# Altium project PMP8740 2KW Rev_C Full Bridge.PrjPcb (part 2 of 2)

## Sheet PMP8740 2KW Rev_C Full Bridge Control Section-A Schematic.SchDoc: Control
size 431 x 279 mm; Date: Not shown in title block; ApprovedBy: Not shown in title block; CheckedBy: Not shown in title block; Author: Not shown in title block; CompanyName: Not shown in title block; DrawnBy: R. Scibilia; Engineer: Not shown in title block; Organization: Not shown in title block; Address1: Not shown in title block; Address2: Not shown in title block; Address3: Not shown in title block; Address4: Not shown in title block; DocumentNumber: 1; Revision: Use project parameter SCH_Rev; SheetNumber: 1; SheetTotal: 1; PageSetup: Record=PageOptions|CenterHorizontal=True|CenterVertical=True|PrintScale=1.00|XCorrection=1.00|YCorrection=1.00|PrintKind=0|BorderSize=5000000|LeftOffset=0|BottomOffset=0|Orientation=2|PaperLength=1000|PaperWidth=1000|Scale=100|PaperSource=15|PrintQuality=600|MediaType=1|DitherType=10|PaperKind=Letter|PrintScaleMode=1
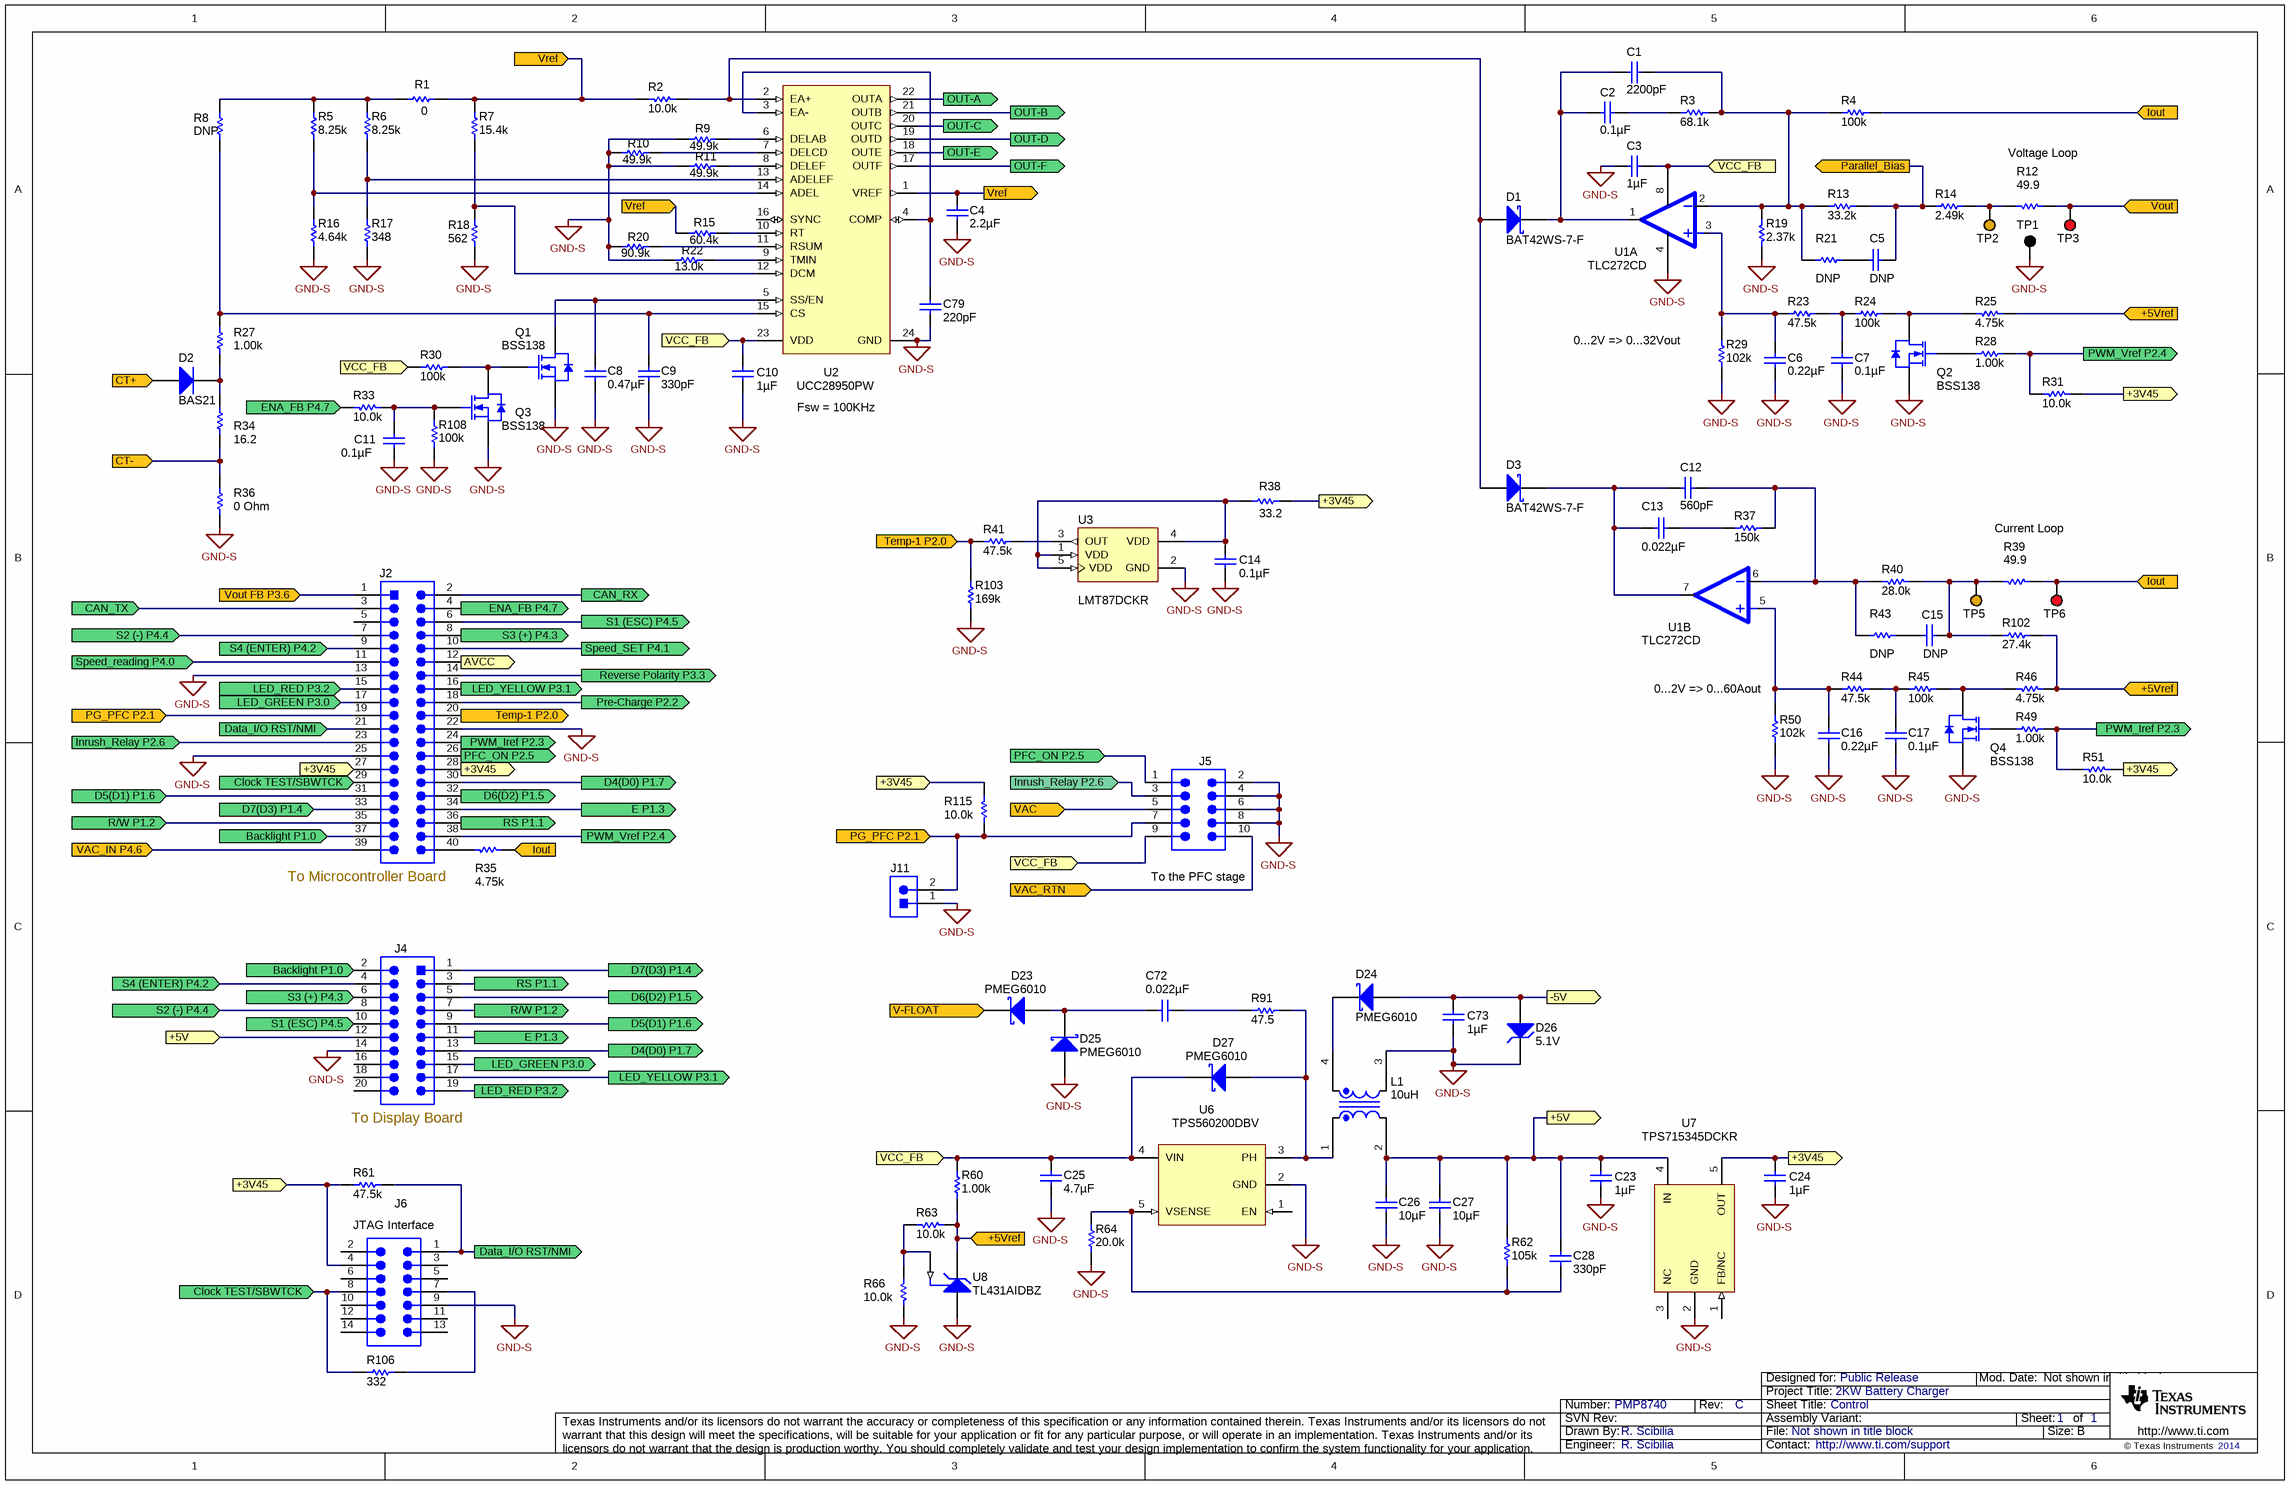
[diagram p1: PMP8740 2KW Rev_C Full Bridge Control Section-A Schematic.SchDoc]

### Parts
C1  ValueDisplayed: 2200pF  [0603]  (hidden comment: C1608C0G1H222J)
C2  ValueDisplayed: 0.1µF  [0603]  (hidden comment: C1608X7R1H104K)
C3  ValueDisplayed: 1µF  [0603]  (hidden comment: C1608X7R1E105K080AB)
C4  ValueDisplayed: 2.2µF  [0805_HV]  (hidden comment: C2012X7R1C225K)
C5  DNP  [0603]
C6  ValueDisplayed: 0.22µF  [0603]  (hidden comment: C1608X7R1C224K)
C7  ValueDisplayed: 0.1µF  [0603]  (hidden comment: C1608X7R1H104K)
C8  ValueDisplayed: 0.47µF  [0805_HV]  (hidden comment: C2012X7R1C474K)
C9  ValueDisplayed: 330pF  [0603]  (hidden comment: C1608C0G1H331J)
C10  ValueDisplayed: 1µF  [0603]  (hidden comment: C1608X7R1E105K080AB)
C11  ValueDisplayed: 0.1µF  [0603]  (hidden comment: C1608X7R1H104K)
C12  ValueDisplayed: 560pF  [0603]  (hidden comment: C1608C0G1H561J)
C13  ValueDisplayed: 0.022µF  [0603]  (hidden comment: C1608X7R2A223K)
C14  ValueDisplayed: 0.1µF  [0603]  (hidden comment: C1608X7R1H104K)
C15  DNP  [0603]
C16  ValueDisplayed: 0.22µF  [0603]  (hidden comment: C1608X7R1C224K)
C17  ValueDisplayed: 0.1µF  [0603]  (hidden comment: C1608X7R1H104K)
C23  ValueDisplayed: 1µF  [0603]  (hidden comment: C1608X7R1E105K080AB)
C24  ValueDisplayed: 1µF  [0603]  (hidden comment: C1608X7R1E105K080AB)
C25  ValueDisplayed: 4.7µF  [1206]  (hidden comment: C3216X7R1E475K)
C26  ValueDisplayed: 10µF  [1206]  (hidden comment: C3216X7R1A106M)
C27  ValueDisplayed: 10µF  [1206]  (hidden comment: C3216X7R1A106M)
C28  ValueDisplayed: 330pF  [0603]  (hidden comment: C1608C0G1H331J)
C72  ValueDisplayed: 0.022µF  [0603]  (hidden comment: C1608X7R2A223K)
C73  ValueDisplayed: 1µF  [0603]  (hidden comment: C1608X7R1E105K080AB)
C79  ValueDisplayed: 220pF  [0603]  (hidden comment: C0603C221J5GACTU)
D1  BAT42WS-7-F  [sod-323]
D2  value BAS21  [SOT-23]  (hidden comment: BAS21-7-F)
D3  BAT42WS-7-F  [sod-323]
D23  value PMEG6010  [SOD-123F]  (hidden comment: PMEG6010CEH,115)
D24  value PMEG6010  [SOD-123F]  (hidden comment: PMEG6010CEH,115)
D25  value PMEG6010  [SOD-123F]  (hidden comment: PMEG6010CEH,115)
D26  value 5.1V  [SOD-123]  (hidden comment: MMSZ4689T1G)
D27  value PMEG6010  [SOD-123F]  (hidden comment: PMEG6010CEH,115)
J2  87758-4016  [MOLEX_87758-4016]  (value not drawn)
J4  66506-072LF  [CONN_66506-072LF]  (value not drawn)
J5  5103308-1  [CONN_5103308-1]  (value not drawn)
J6  SBH11-PBPC-D07-ST-BK  [CONN_SBH11-PBPC-D07-ST-BK]  (value not drawn)
J11  5-146261-1  [CONN_5-146261-1]  (value not drawn)
L1  value 10uH  [WE-DD_7332]  (hidden comment: 744878100)
Q1  BSS138  [SOT-23]
Q2  BSS138  [SOT-23]
Q3  BSS138  [SOT-23]
Q4  BSS138  [SOT-23]
R1  value 0  [0603]  (hidden comment: CRCW06031R00FKEA)
R2  value 10.0k  [0603]  (hidden comment: CRCW060310K0FKEA)
R3  ValueDisplayed: 68.1k  [0603]  (hidden comment: CRCW060368K1FKEA)
R4  value 100k  [0603]  (hidden comment: CRCW0603100KFKEA)
R5  value 8.25k  [0603]  (hidden comment: CRCW06038K25FKEA)
R6  value 8.25k  [0603]  (hidden comment: CRCW06038K25FKEA)
R7  value 15.4k  [0603]  (hidden comment: CRCW060315K4FKEA)
R8  value DNP  [0603]  (hidden comment: Do Not Populate)
R9  value 49.9k  [0603]  (hidden comment: CRCW060349K9FKEA)
R10  value 49.9k  [0603]  (hidden comment: CRCW060349K9FKEA)
R11  value 49.9k  [0603]  (hidden comment: CRCW060349K9FKEA)
R12  value 49.9  [0603]  (hidden comment: CRCW060349R9FKEA)
R13  ValueDisplayed: 33.2k  [1206]  (hidden comment: CRCW120633K2FKEA)
R14  value 2.49k  [0603]  (hidden comment: CRCW06032K49FKEA)
R15  value 60.4k  [0603]  (hidden comment: CRCW060360K4FKEA)
R16  value 4.64k  [0603]  (hidden comment: CRCW06034K64FKEA)
R17  value 348  [0603]  (hidden comment: CRCW0603348RFKEA)
R18  ValueDisplayed: 562  [0603]  (hidden comment: CRCW0603562RFKEA)
R19  value 2.37k  [0603]  (hidden comment: CRCW06032K37FKEA)
R20  value 90.9k  [0603]  (hidden comment: CRCW060390K9FKEA)
R21  DNP  [0603]
R22  value 13.0k  [0603]  (hidden comment: CRCW060313K0FKEA)
R23  ValueDisplayed: 47.5k  [0603]  (hidden comment: CRCW060347K5FKEA)
R24  value 100k  [0603]  (hidden comment: CRCW0603100KFKEA)
R25  value 4.75k  [0603]  (hidden comment: CRCW06034K75FKEA)
R27  value 1.00k  [0603]  (hidden comment: CRCW06031K00FKEA)
R28  value 1.00k  [0603]  (hidden comment: CRCW06031K00FKEA)
R29  ValueDisplayed: 102k  [0603]  (hidden comment: CRCW0603102KFKEA)
R30  value 100k  [0603]  (hidden comment: CRCW0603100KFKEA)
R31  value 10.0k  [0603]  (hidden comment: CRCW060310K0FKEA)
R33  value 10.0k  [0603]  (hidden comment: CRCW060310K0FKEA)
R34  ValueDisplayed: 16.2  [2512]  (hidden comment: CRCW251216R2FKEG)
R35  value 4.75k  [0603]  (hidden comment: CRCW06034K75FKEA)
R36  0 Ohm  [1206]
R37  ValueDisplayed: 150k  [0603]  (hidden comment: CRCW0603150KFKEA)
R38  value 33.2  [0603]  (hidden comment: CRCW060333R2FKEA)
R39  value 49.9  [0603]  (hidden comment: CRCW060349R9FKEA)
R40  value 28.0k  [0603]  (hidden comment: CRCW060328K0FKEA)
R41  ValueDisplayed: 47.5k  [0603]  (hidden comment: CRCW060347K5FKEA)
R43  DNP  [0603]
R44  ValueDisplayed: 47.5k  [0603]  (hidden comment: CRCW060347K5FKEA)
R45  value 100k  [0603]  (hidden comment: CRCW0603100KFKEA)
R46  value 4.75k  [0603]  (hidden comment: CRCW06034K75FKEA)
R49  value 1.00k  [0603]  (hidden comment: CRCW06031K00FKEA)
R50  ValueDisplayed: 102k  [0603]  (hidden comment: CRCW0603102KFKEA)
R51  value 10.0k  [0603]  (hidden comment: CRCW060310K0FKEA)
R60  value 1.00k  [0603]  (hidden comment: CRCW06031K00FKEA)
R61  ValueDisplayed: 47.5k  [0603]  (hidden comment: CRCW060347K5FKEA)
R62  value 105k  [0603]  (hidden comment: CRCW0603105KFKEA)
R63  value 10.0k  [0603]  (hidden comment: CRCW060310K0FKEA)
R64  value 20.0k  [0603]  (hidden comment: CRCW060320K0FKEA)
R66  value 10.0k  [0603]  (hidden comment: CRCW060310K0FKEA)
R91  value 47.5  [0805_HV]  (hidden comment: CRCW080547R5FKEA)
R102  ValueDisplayed: 27.4k  [0603]  (hidden comment: CRCW060327K4FKEA)
R103  ValueDisplayed: 169k  [0603]  (hidden comment: CRCW0603169KFKEA)
R106  value 332  [0603]  (hidden comment: RC0603FR-07332RL)
R108  value 100k  [0603]  (hidden comment: CRCW0603100KFKEA)
R115  value 10.0k  [0603]  (hidden comment: CRCW060310K0FKEA)
TP1  5006  [Keystone5006]  (value not drawn)
TP2  5008  [Keystone5008]  (value not drawn)
TP3  5005  [Keystone5005]  (value not drawn)
TP5  5008  [Keystone5008]  (value not drawn)
TP6  5005  [Keystone5005]  (value not drawn)
U1  TLC272CD  [SO8]  (parts A,B of 2)
U2  UCC28950PW  [PW0024A_N]
U3  value LMT87DCKR  [MAA05A_N]  (hidden comment: LM94022QBIMG)
U6  TPS560200DBV  [DBV0005A_N]
U7  TPS715345DCKR  [DCK0005A_N]
U8  TL431AIDBZ  [DBZ0003A_N]

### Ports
+3V45, +5V, +5Vref, -5V, AVCC, Backlight P1.0, CAN_RX, CAN_TX, Clock TEST/SBWTCK, CT+, CT-, D4(D0) P1.7, D5(D1) P1.6, D6(D2) P1.5, D7(D3) P1.4, Data_I/O RST/NMI, E P1.3, ENA_FB P4.7, Inrush_Relay P2.6, Iout, LED_GREEN P3.0, LED_RED P3.2, LED_YELLOW P3.1, OUT-A, OUT-B, OUT-C, OUT-D, OUT-E, OUT-F, Parallel_Bias, PFC_ON P2.5, PG_PFC P2.1, Pre-Charge P2.2, PWM_Iref P2.3, PWM_Vref P2.4, R/W P1.2, Reverse Polarity P3.3, RS P1.1, S1 (ESC) P4.5, S2 (-) P4.4, S3 (+) P4.3, S4 (ENTER) P4.2, Speed_reading P4.0, Speed_SET P4.1, Temp-1 P2.0, V-FLOAT, VAC, VAC_IN P4.6, VAC_RTN, VCC_FB, Vout, Vout FB P3.6, Vref

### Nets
GND-S: C3.1 C4.2 C6.2 C7.2 C8.2 C9.2 C10.2 C11.2 C14.2 C16.2 C17.2 C23.2 C24.2 C25.2 C26.2 C27.2 C73.2 C79.2 D25.2(A) D26.1(K) J2.13 J2.22 J2.25 J4.14 J5.2 J5.4 J5.6 J5.8 J6.9 J11.1 L1.3 Q1.2(S) Q2.2(S) Q3.2(S) Q4.2(S) R9.1 R10.1 R11.1 R16.1 R17.1 R18.1 R19.1 R20.1 R22.1 R29.1 R36.2 R50.1 R64.1 R66.1 R103.1 R108.1 TP1.1 U1.4(GND) U2.24(GND) U3.2(GND) U6.2(GND) U7.2(GND) U8.3(ANODE)
+3V45: C24.1 J2.27 J2.28 J6.4 R31.2 R38.2 R51.2 R61.1 R115.2 U7.5(OUT) ; port +3V45
+5V: C23.1 C26.1 C27.1 C28.1 J4.12 L1.2 R62.2 U7.4(IN) ; port +5V
+5Vref: R25.1 R46.1 R60.1 R63.2 R102.2 U8.1(CATHODE) ; port +5Vref
-5V: C73.1 D24.2(A) D26.2(A) ; port -5V
AVCC: J2.12 ; port AVCC
Backlight P1.0: J2.37 J4.2 ; port Backlight P1.0
CAN_RX: J2.2 ; port CAN_RX
CAN_TX: J2.3 ; port CAN_TX
Clock TEST/SBWTCK: J2.29 J6.8 R106.1 ; port Clock TEST/SBWTCK
CT+: D2.1(A) ; port CT+
CT-: R34.1 R36.1 ; port CT-
D4(D0) P1.7: J2.30 J4.13 ; port D4(D0) P1.7
D5(D1) P1.6: J2.31 J4.9 ; port D5(D1) P1.6
D6(D2) P1.5: J2.32 J4.5 ; port D6(D2) P1.5
D7(D3) P1.4: J2.33 J4.1 ; port D7(D3) P1.4
Data_I/O RST/NMI: J2.21 J6.1 R61.2 ; port Data_I/O RST/NMI
E P1.3: J2.34 J4.11 ; port E P1.3
ENA_FB P4.7: J2.4 R33.2 ; port ENA_FB P4.7
Inrush_Relay P2.6: J2.23 J5.3 ; port Inrush_Relay P2.6
Iout: R4.1 R35.2 R39.1 TP6.1 ; port Iout
LED_GREEN P3.0: J2.17 J4.15 ; port LED_GREEN P3.0
LED_RED P3.2: J2.15 J4.19 ; port LED_RED P3.2
LED_YELLOW P3.1: J2.16 J4.17 ; port LED_YELLOW P3.1
OUT-A: U2.22(OUTA) ; port OUT-A
OUT-B: U2.21(OUTB) ; port OUT-B
OUT-C: U2.20(OUTC) ; port OUT-C
OUT-D: U2.19(OUTD) ; port OUT-D
OUT-E: U2.18(OUTE) ; port OUT-E
OUT-F: U2.17(OUTF) ; port OUT-F
Parallel_Bias: C5.1 R13.2 R14.2 ; port Parallel_Bias
PFC_ON P2.5: J2.26 J5.1 ; port PFC_ON P2.5
PG_PFC P2.1: J2.19 J5.7 J11.2 R115.1 ; port PG_PFC P2.1
Pre-Charge P2.2: J2.18 ; port Pre-Charge P2.2
PWM_Iref P2.3: J2.24 R49.1 R51.1 ; port PWM_Iref P2.3
PWM_Vref P2.4: J2.38 R28.1 R31.1 ; port PWM_Vref P2.4
R/W P1.2: J2.35 J4.7 ; port R/W P1.2
Reverse Polarity P3.3: J2.14 ; port Reverse Polarity P3.3
RS P1.1: J2.36 J4.3 ; port RS P1.1
S1 (ESC) P4.5: J2.6 J4.10 ; port S1 (ESC) P4.5
S2 (-) P4.4: J2.7 J4.8 ; port S2 (-) P4.4
S3 (+) P4.3: J2.8 J4.6 ; port S3 (+) P4.3
S4 (ENTER) P4.2: J2.9 J4.4 ; port S4 (ENTER) P4.2
Speed_reading P4.0: J2.11 ; port Speed_reading P4.0
Speed_SET P4.1: J2.10 ; port Speed_SET P4.1
Temp-1 P2.0: J2.20 R41.2 R103.2 ; port Temp-1 P2.0
V-FLOAT: D23.1(K) ; port V-FLOAT
VAC: J5.5 ; port VAC
VAC_IN P4.6: J2.39 ; port VAC_IN P4.6
VAC_RTN: J5.10 ; port VAC_RTN
VCC_FB: C3.2 C10.1 C25.1 D27.1(K) J5.9 R30.1 R60.2 U1.8(VCC) U2.23(VDD) U6.4(VIN) ; port VCC_FB
Vout: R12.1 TP3.1 ; port Vout
Vout FB P3.6: J2.1 ; port Vout FB P3.6
Vref: C4.1 R1.2 R2.2 R7.2 R15.2 U2.1(VREF) ; port Vref
NetC1_1: C1.1 C2.1 D1.1(K) U1.1(OUT1)
NetC1_2: C1.2 R3.1 R4.2 R13.1 R19.2 R21.1 U1.2(IN-)
NetC2_2: C2.2 R3.2
NetC5_2: C5.2 R21.2
NetC6_1: C6.1 R23.1 R29.2 U1.3(IN+)
NetC7_1: C7.1 R23.2 R24.1
NetC8_1: C8.1 Q1.3(D) U2.5(SS/EN)
NetC9_1: C9.1 R8.1 R27.1 U2.15(CS)
NetC11_1: C11.1 Q3.1(G) R33.1 R108.2
NetC12_1: C12.1 C13.1 D3.1(K) U1.7(OUT)
NetC12_2: C12.2 R37.1 R40.2 R43.1 U1.6(IN-)
NetC13_2: C13.2 R37.2
NetC14_1: C14.1 R38.1 U3.1(VDD) U3.4(VDD) U3.5(VDD)
NetC15_1: C15.1 R39.2 R40.1 R102.1 TP5.1
NetC15_2: C15.2 R43.2
NetC16_1: C16.1 R44.1 R50.2 U1.5(IN+)
NetC17_1: C17.1 R44.2 R45.1
NetC28_2: C28.2 R62.1 R64.2 U6.5(VSENSE)
NetC72_1: C72.1 D23.2(A) D25.1(K)
NetC72_2: C72.2 R91.1
NetC79_1: C79.1 U2.3(EA-) U2.4(COMP)
NetD1_2: D1.2(A) D3.2(A) R2.1 U2.2(EA+)
NetD2_3: D2.3(K) R27.2 R34.2
NetD24_1: D24.1(K) L1.4
NetD27_2: D27.2(A) L1.1 R91.2 U6.3(PH)
NetJ2_40: J2.40 R35.1
NetJ6_7: J6.7 R106.2
NetQ1_1: Q1.1(G) Q3.3(D) R30.2
NetQ2_1: Q2.1(G) R28.2
NetQ2_3: Q2.3(D) R24.2 R25.2
NetQ4_1: Q4.1(G) R49.2
NetQ4_3: Q4.3(D) R45.2 R46.2
NetR1_1: R1.1 R5.2 R6.2 R8.2
NetR5_1: R5.1 R16.2 U2.14(ADEL)
NetR6_1: R6.1 R17.2 U2.13(ADELEF)
NetR7_1: R7.1 R18.2 U2.12(DCM)
NetR9_2: R9.2 U2.6(DELAB)
NetR10_2: R10.2 U2.7(DELCD)
NetR11_2: R11.2 U2.8(DELEF)
NetR12_2: R12.2 R14.1 TP2.1
NetR15_1: R15.1 U2.10(RT)
NetR20_2: R20.2 U2.11(RSUM)
NetR22_2: R22.2 U2.9(TMIN)
NetR41_1: R41.1 U3.3(OUT)
NetR63_1: R63.1 R66.2 U8.2(REF)

Not connected (* = marked no-connect by the designer): J2 5; J4 16 18 20; J6 2 3 5 6 10 11 12 13 14; U2 16(SYNC); U6 1(EN); U7 1(FB/NC) 3(NC)

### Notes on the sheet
- Voltage Loop
- (near R29) 0...2V => 0...32Vout
- Fsw = 100KHz
- Current Loop
- (near R50) 0...2V => 0...60Aout
- To Microcontroller Board
- (near J5) To the PFC stage
- (near J4) To Display Board
- JTAG Interface

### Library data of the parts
C1 = C1608C0G1H222J: CAP, CERM, 2200 pF, 50 V, +/- 5%, C0G/NP0, 0603; Manufacturer: TDK; Polarized: N; CompType: Capacitor; Value: 2200pF; U/M: EA; Cap_F: 0.0000000022; Tolerance_%: 5; ESR_ohm: 0.0375; Value1: 0.0375 ohm; VDC_V: 50; Value2: 50V; TaMin_C: -55; TaMax_C: 125
C2 C7 C11 C14 C17 = C1608X7R1H104K: CAP, CERM, 0.1uF, 50V, +/-10%, X7R, 0603; Manufacturer: TDK; Polarized: N; CompType: Capacitor; U/M: EA; Cap_F: 0.0000001; Tolerance_%: 10; ESR_Ohm: 0.017; Value1: 0.017 ohm; VDC_V: 50; TaMin_C: -55; TaMax_C: 125
C3 C10 C23 C24 C73 = C1608X7R1E105K080AB: CAP, CERM, 1uF, 25V, +/-10%, X7R, 0603; Manufacturer: TDK; Polarized: N; CompType: Capacitor; U/M: EA; Cap_F: 0.000001; Tolerance_%: 10; Value1: Unknown; VDC_V: 25; TaMin_C: -55; TaMax_C: 125
C4 = C2012X7R1C225K: CAP, CERM, 2.2uF, 16V, +/-10%, X7R, 0805; Manufacturer: TDK; Polarized: N; CompType: Capacitor; U/M: EA; Cap_F: 0.0000022; Tolerance_%: 10; ESR_Ohm: 0.0049; Value1: 0.0049 ohm; VDC_V: 16; TaMin_C: -55; TaMax_C: 125; Cap_Case: 0805
C5 C15 = C1608X7R2A223K: Manufacturer: TDK; Polarized: N; CompType: Capacitor; ValueDisplayed: 0.022µF; U/M: EA; Cap_F: 0.000000022; Tolerance_%: 10; ESR_Ohm: 0.037; Value1: 0.037 ohm; VDC_V: 100; Value2: 100V; TempCo: X7R; TaMin_C: -55; TaMax_C: 125
C6 C16 = C1608X7R1C224K: CAP, CERM, 0.22uF, 16V, +/-10%, X7R, 0603; Manufacturer: TDK; Polarized: N; CompType: Capacitor; U/M: EA; Cap_F: 0.00000022; Tolerance_%: 10; ESR_Ohm: 0.0125; Value1: 0.0125 ohm; VDC_V: 16; TaMin_C: -55; TaMax_C: 125
C8 = C2012X7R1C474K: CAP, CERM, 0.47uF, 16V, +/-10%, X7R, 0805; Manufacturer: TDK; Polarized: N; CompType: Capacitor; U/M: EA; Cap_F: 0.00000047; Tolerance_%: 10; ESR_Ohm: 0.0101; Value1: 0.0101 ohm; VDC_V: 16; TaMin_C: -55; TaMax_C: 125; Cap_Case: 0805
C9 C28 = C1608C0G1H331J: CAP, CERM, 330pF, 50V, +/-5%, C0G/NP0, 0603; Manufacturer: TDK; Polarized: N; CompType: Capacitor; U/M: EA; Cap_F: 0.00000000033; Tolerance_%: 5; ESR_Ohm: 0.1096; Value1: 0.1096 ohm; VDC_V: 50; TaMin_C: -55; TaMax_C: 125
C12 = C1608C0G1H561J: CAP, CERM, 560pF, 50V, +/-5%, C0G/NP0, 0603; Manufacturer: TDK; Polarized: N; CompType: Capacitor; U/M: EA; Cap_F: 0.00000000056; Tolerance_%: 5; ESR_Ohm: 0.0858; Value1: 0.0858 ohm; VDC_V: 50; TaMin_C: -55; TaMax_C: 125
C13 C72 = C1608X7R2A223K: CAP, CERM, 0.022uF, 100V, +/-10%, X7R, 0603; Manufacturer: TDK; Polarized: N; CompType: Capacitor; U/M: EA; Cap_F: 0.000000022; Tolerance_%: 10; ESR_Ohm: 0.037; Value1: 0.037 ohm; VDC_V: 100; TaMin_C: -55; TaMax_C: 125
C25 = C3216X7R1E475K: CAP, CERM, 4.7uF, 25V, +/-10%, X7R, 1206; Manufacturer: TDK; Polarized: N; CompType: Capacitor; U/M: EA; Cap_F: 0.0000047; Tolerance_%: 10; ESR_Ohm: 0.0063; Value1: 0.0063 ohm; VDC_V: 25; TaMin_C: -55; TaMax_C: 125
C26 C27 = C3216X7R1A106M: CAP, CERM, 10uF, 10V, +/-20%, X7R, 1206; Manufacturer: TDK; Polarized: N; CompType: Capacitor; U/M: EA; Cap_F: 0.00001; Tolerance_%: 20; ESR_Ohm: 0.0046; Value1: 0.0046 ohm; VDC_V: 10; TaMin_C: -55; TaMax_C: 125
C79 = C0603C221J5GACTU: CAP, CERM, 220pF, 50V, +/-5%, C0G/NP0, 0603; Manufacturer: Kemet; Polarized: N; CompType: Capacitor; U/M: EA; Cap_F: 0.00000000022; Tolerance_%: 5; Value1: Unknown; VDC_V: 50; TaMin_C: -55; TaMax_C: 125
D1 D3 = BAT42WS-7-F: Diode, Schottky, 30 V, 0.2 A, SOD-323; Manufacturer: Diodes Inc.; U/M: EA; Vf_V: 1; Value: 30V; Value1: 0.2A; Value2: 1V; Io_A: 0.2; Vr_V: 30
D2 = BAS21-7-F: Diode, Switching, 200V, 0.2A, SOT-23; Manufacturer: Diodes Inc.; U/M: EA; Vf_V: 1.25; Value2: 1.25V; Io_A: 0.2; Vr_V: 200; TJmax_C: 150; RJC_CperW: 500
D23-D25 D27 = PMEG6010CEH,115: Diode, Schottky, 60 V, 1 A, SOD-123F; Manufacturer: NXP Semiconductor; U/M: EA; Vf_V: 0.57; Value1: 1A; Value2: 0.57V; Io_A: 1; Vr_V: 60; TJmax_C: 150
D26 = MMSZ4689T1G: Diode, Zener, 5.1 V, 500 mW, SOD-123; Manufacturer: ON Semiconductor; SymbolCreator: a0412235; U/M: EA; Power_W: 0.5; Vz_V: 5.1; Value1: 0.5W; RJA_CperW: 340
J2 = 87758-4016: Header, 2mm, 20x2, Gold, TH; Manufacturer: Molex; SymbolCreator: a0412235; U/M: EA
J4 = 66506-072LF: Header (shrouded), 100mil, 10x2, Gold plated, TH; Manufacturer: FCI; SymbolCreator: a0412235; Note: Need STEP model; U/M: EA
J5 = 5103308-1: Header (shrouded), 100mil, 5x2, Gold, TH; Manufacturer: TE Connectivity; SymbolCreator: a0412235; CompType: Connector; U/M: EA
J6 = SBH11-PBPC-D07-ST-BK: Header (shrouded), 100 mil, 7x2, Gold plated, TH; Manufacturer: Sullins Connector Solutions; SymbolCreator: a0412235; CompType: Connector; U/M: EA
J11 = 5-146261-1: Header, 100mil, 2x1, Gold, TH; Manufacturer: TE Connectivity; SymbolCreator: a0412235; U/M: EA
L1 = 744878004: Coupled inductor, 10 µH, 1 A, 0.14 ohm, +/- 20%, SMD; Manufacturer: Wurth Elektronik eiSos; SymbolCreator: a0412235; ValueDisplayed: 4.7µH; Ind_H: 4.7E-6; DCR_ohm: 0.065; Isat: 2; Tolerance_%: 20
Q1-Q4 = BSS138: MOSFET, N-CH, 50V, 0.22A, SOT-23; Manufacturer: Fairchild Semiconductor; Alternate Manufacturer: None; U/M: EA; ChType: N; VdsMax_V: 50; Value1: 6 ohm; Rdson45_Ohm: 6; Value2: 1.7 nC; QgTyp_nC: 1.7; Vgs_V: 20; IdsMax_A: 0.22
R1 = CRCW06031R00FKEA: RES, 0 ohm, 1%, 0.1W, 0603; Manufacturer: Vishay-Dale; CompType: Resistor; Res_ohm: 1; Value_Code: 1R00; Power_W: 0.1; VDC_V: 75; TempCo: 100 ppm/C; EIA_Code: E96; U/M: EA
R2 R31 R33 R51 R63 R66 R115 = CRCW060310K0FKEA: RES, 10.0k ohm, 1%, 0.1W, 0603; Manufacturer: Vishay-Dale; CompType: Resistor; Res_ohm: 10000; Value_Code: 10k0; Tolerance_%: 1; Power_W: 0.1; VDC_V: 75; TempCo: 100 ppm/C; EIA_Code: E96; U/M: EA
R3 = CRCW060368K1FKEA: RES, 68.1 k, 1%, 0.1 W, 0603; Manufacturer: Vishay-Dale; CompType: Resistor; Value: 68.1k; Res_ohm: 68100; Value_Code: 68k1; Tolerance_%: 1; Power_W: 0.1; Value2: 0.1W; VDC_V: 75; TempCo: 100 ppm/C; EIA_Code: E96; U/M: EA
R4 R24 R30 R45 R108 = CRCW0603100KFKEA: RES, 100k ohm, 1%, 0.1W, 0603; Manufacturer: Vishay-Dale; CompType: Resistor; Res_ohm: 100000; Tolerance_%: 1; Power_W: 0.1; VDC_V: 75; TempCo: 100 ppm/C; EIA_Code: E96; U/M: EA
R5 R6 = CRCW06038K25FKEA: RES, 8.25k ohm, 1%, 0.1W, 0603; Manufacturer: Vishay-Dale; CompType: Resistor; Res_ohm: 8250; Value_Code: 8k25; Tolerance_%: 1; Power_W: 0.1; VDC_V: 75; TempCo: 100 ppm/C; EIA_Code: E96; U/M: EA
R7 = CRCW060315K4FKEA: RES, 15.4k ohm, 1%, 0.1W, 0603; Manufacturer: Vishay-Dale; CompType: Resistor; Res_ohm: 15400; Value_Code: 15k4; Tolerance_%: 1; Power_W: 0.1; VDC_V: 75; TempCo: 100 ppm/C; EIA_Code: E96; U/M: EA
R8 = CRCW06031R00FKEA: Manufacturer: Vishay-Dale; CompType: Resistor; Res_ohm: 1; Value_Code: 1R00; Value1: 1%; Power_W: 0.1; Value2: 0.1W; VDC_V: 75; TempCo: 100 ppm/C; EIA_Code: E96; U/M: EA
R9-R11 = CRCW060349K9FKEA: RES, 49.9k ohm, 1%, 0.1W, 0603; Manufacturer: Vishay-Dale; CompType: Resistor; Res_ohm: 49900; Value_Code: 49k9; Tolerance_%: 1; Power_W: 0.1; VDC_V: 75; TempCo: 100 ppm/C; EIA_Code: E96; U/M: EA
R12 R39 = CRCW060349R9FKEA: RES, 49.9 ohm, 1%, 0.1W, 0603; Manufacturer: Vishay-Dale; CompType: Resistor; Value_Code: 49R9; Tolerance_%: 1; Power_W: 0.1; VDC_V: 75; TempCo: 100 ppm/C; EIA_Code: E96; U/M: EA
R13 = CRCW120633K2FKEA: RES, 33.2 k, 1%, 0.25 W, 1206; Manufacturer: Vishay-Dale; CompType: Resistor; Value: 33.2k; Res_ohm: 33200; Value_Code: 33k2; Tolerance_%: 1; Power_W: 0.25; Value2: 0.25W; VDC_V: 200; TempCo: 100 ppm/C; EIA_Code: E96; U/M: EA
R14 = CRCW06032K49FKEA: RES, 2.49k ohm, 1%, 0.1W, 0603; Manufacturer: Vishay-Dale; CompType: Resistor; Res_ohm: 2490; Value_Code: 2k49; Tolerance_%: 1; Power_W: 0.1; VDC_V: 75; TempCo: 100 ppm/C; EIA_Code: E96; U/M: EA
R15 = CRCW060360K4FKEA: RES, 60.4k ohm, 1%, 0.1W, 0603; Manufacturer: Vishay-Dale; CompType: Resistor; Res_ohm: 60400; Value_Code: 60k4; Tolerance_%: 1; Power_W: 0.1; VDC_V: 75; TempCo: 100 ppm/C; EIA_Code: E96; U/M: EA
R16 = CRCW06034K64FKEA: RES, 4.64k ohm, 1%, 0.1W, 0603; Manufacturer: Vishay-Dale; CompType: Resistor; Res_ohm: 4640; Value_Code: 4k64; Tolerance_%: 1; Power_W: 0.1; VDC_V: 75; TempCo: 100 ppm/C; EIA_Code: E96; U/M: EA
R17 = CRCW0603348RFKEA: RES, 348 ohm, 1%, 0.1W, 0603; Manufacturer: Vishay-Dale; CompType: Resistor; Value_Code: 348R; Tolerance_%: 1; Power_W: 0.1; VDC_V: 75; TempCo: 100 ppm/C; EIA_Code: E96; U/M: EA
R18 = CRCW0603562RFKEA: RES, 562, 1%, 0.1 W, 0603; Manufacturer: Vishay-Dale; CompType: Resistor; Value: 562; Value_Code: 562R; Tolerance_%: 1; Power_W: 0.1; Value2: 0.1W; VDC_V: 75; TempCo: 100 ppm/C; EIA_Code: E96; U/M: EA
R19 = CRCW06032K37FKEA: RES, 2.37k ohm, 1%, 0.1W, 0603; Manufacturer: Vishay-Dale; CompType: Resistor; Res_ohm: 2370; Value_Code: 2k37; Tolerance_%: 1; Power_W: 0.1; VDC_V: 75; TempCo: 100 ppm/C; EIA_Code: E96; U/M: EA
R20 = CRCW060390K9FKEA: RES, 90.9k ohm, 1%, 0.1W, 0603; Manufacturer: Vishay-Dale; CompType: Resistor; Res_ohm: 90900; Value_Code: 90k9; Tolerance_%: 1; Power_W: 0.1; VDC_V: 75; TempCo: 100 ppm/C; EIA_Code: E96; U/M: EA
R21 R43 = CRCW060313K0FKEA: Manufacturer: Vishay-Dale; CompType: Resistor; Res_ohm: 13000; Value_Code: 13k0; Tolerance_%: 1; Value1: 1%; Power_W: 0.1; Value2: 0.1W; VDC_V: 75; TempCo: 100 ppm/C; EIA_Code: E96; U/M: EA
R22 = CRCW060313K0FKEA: RES, 13.0k ohm, 1%, 0.1W, 0603; Manufacturer: Vishay-Dale; CompType: Resistor; Res_ohm: 13000; Value_Code: 13k0; Tolerance_%: 1; Power_W: 0.1; VDC_V: 75; TempCo: 100 ppm/C; EIA_Code: E96; U/M: EA
R23 R41 R44 R61 = CRCW060347K5FKEA: RES, 47.5 k, 1%, 0.1 W, 0603; Manufacturer: Vishay-Dale; CompType: Resistor; Value: 47.5k; Res_ohm: 47500; Value_Code: 47k5; Tolerance_%: 1; Power_W: 0.1; Value2: 0.1W; VDC_V: 75; TempCo: 100 ppm/C; EIA_Code: E96; U/M: EA
R25 R35 R46 = CRCW06034K75FKEA: RES, 4.75k ohm, 1%, 0.1W, 0603; Manufacturer: Vishay-Dale; CompType: Resistor; Res_ohm: 4750; Value_Code: 4k75; Tolerance_%: 1; Power_W: 0.1; VDC_V: 75; TempCo: 100 ppm/C; EIA_Code: E96; U/M: EA
R27 R28 R49 R60 = CRCW06031K00FKEA: RES, 1.00k ohm, 1%, 0.1W, 0603; Manufacturer: Vishay-Dale; CompType: Resistor; Res_ohm: 1000; Value_Code: 1k00; Tolerance_%: 1; Power_W: 0.1; VDC_V: 75; TempCo: 100 ppm/C; EIA_Code: E96; U/M: EA
R29 R50 = CRCW0603102KFKEA: RES, 102 k, 1%, 0.1 W, 0603; Manufacturer: Vishay-Dale; CompType: Resistor; Value: 102k; Res_ohm: 102000; Tolerance_%: 1; Power_W: 0.1; Value2: 0.1W; VDC_V: 75; TempCo: 100 ppm/C; EIA_Code: E96; U/M: EA
R34 = CRCW251216R2FKEG: RES, 16.2, 1%, 1 W, 2512; Manufacturer: Vishay-Dale; CompType: Resistor; Value: 16.2; Value_Code: 16R2; Tolerance_%: 1; Value2: 1W; VDC_V: 500; TempCo: 100 ppm/C; EIA_Code: E96; U/M: EA
R36 = CRCW12061K00FKEA: RES, 0 Ohm, 0.25 W, 1206; Manufacturer: Vishay-Dale; CompType: Resistor; Res_ohm: 1000; Value_Code: 1k00; Tolerance_%: 1; Value1: 1%; Power_W: 0.25; Value2: 0.25W; VDC_V: 200; TempCo: 100 ppm/C; EIA_Code: E96; U/M: EA
R37 = CRCW0603150KFKEA: RES, 150 k, 1%, 0.1 W, 0603; Manufacturer: Vishay-Dale; CompType: Resistor; Value: 150k; Res_ohm: 150000; Tolerance_%: 1; Power_W: 0.1; Value2: 0.1W; VDC_V: 75; TempCo: 100 ppm/C; EIA_Code: E96; U/M: EA
R38 = CRCW060333R2FKEA: RES, 33.2 ohm, 1%, 0.1W, 0603; Manufacturer: Vishay-Dale; CompType: Resistor; Value_Code: 33R2; Tolerance_%: 1; Power_W: 0.1; VDC_V: 75; TempCo: 100 ppm/C; EIA_Code: E96; U/M: EA
R40 = CRCW060328K0FKEA: RES, 28.0k ohm, 1%, 0.1W, 0603; Manufacturer: Vishay-Dale; CompType: Resistor; Res_ohm: 28000; Value_Code: 28k0; Tolerance_%: 1; Power_W: 0.1; VDC_V: 75; TempCo: 100 ppm/C; EIA_Code: E96; U/M: EA
R62 = CRCW0603105KFKEA: RES, 105k ohm, 1%, 0.1W, 0603; Manufacturer: Vishay-Dale; CompType: Resistor; Res_ohm: 105000; Tolerance_%: 1; Power_W: 0.1; VDC_V: 75; TempCo: 100 ppm/C; EIA_Code: E96; U/M: EA
R64 = CRCW060320K0FKEA: RES, 20.0k ohm, 1%, 0.1W, 0603; Manufacturer: Vishay-Dale; CompType: Resistor; Res_ohm: 20000; Value_Code: 20k0; Tolerance_%: 1; Power_W: 0.1; VDC_V: 75; TempCo: 100 ppm/C; EIA_Code: E96; U/M: EA
R91 = CRCW080547R5FKEA: RES, 47.5 ohm, 1%, 0.125W, 0805; Manufacturer: Vishay-Dale; CompType: Resistor; Value_Code: 47R5; Tolerance_%: 1; Power_W: 0.125; VDC_V: 150; TempCo: 100 ppm/C; EIA_Code: E96; U/M: EA
R102 = CRCW060327K4FKEA: RES, 27.4 k, 1%, 0.1 W, 0603; Manufacturer: Vishay-Dale; CompType: Resistor; Value: 27.4k; Res_ohm: 27400; Value_Code: 27k4; Tolerance_%: 1; Power_W: 0.1; Value2: 0.1W; VDC_V: 75; TempCo: 100 ppm/C; EIA_Code: E96; U/M: EA
R103 = CRCW0603169KFKEA: RES, 169 k, 1%, 0.1 W, 0603; Manufacturer: Vishay-Dale; CompType: Resistor; Value: 169k; Res_ohm: 169000; Tolerance_%: 1; Power_W: 0.1; Value2: 0.1W; VDC_V: 75; TempCo: 100 ppm/C; EIA_Code: E96; U/M: EA
R106 = RC0603FR-07332RL: RES, 332 ohm, 1%, 0.1W, 0603; Manufacturer: Yageo America; CompType: Resistor; Value_Code: 332R; Tolerance_%: 1; Power_W: 0.1; VDC_V: 150; TempCo: 200 ppm/C; EIA_Code: E96; U/M: EA
TP1 = 5006: Test Point, Compact, Black, TH; Manufacturer: Keystone; CompType: Test Point Loop; U/M: EA
TP2 TP5 = 5008: Test Point, Compact, Orange, TH; Manufacturer: Keystone; CompType: Test Point Loop; U/M: EA
TP3 TP6 = 5005: Test Point, Compact, Red, TH; Manufacturer: Keystone; CompType: Test Point Loop; U/M: EA
U1 = TLC272CD: IC, Precision Dual Operational Amplifiers; Manufacturer: TI; Alternate Manufacturer: None; Area: 75900
U2 = UCC28950PW: Green Phase-Shifted Full-Bridge Controller with Synchronous Rectification with Current Control, 97 % Duty Cycle, -40 to +125 degC, 24-pin TSSOP (PW), Green (RoHS & no Sb/Br); Manufacturer: Texas Instruments; Alternate Manufacturer: None; Alternate PartNumber: Equivalent; Duty Cycle(Max)(%): 97; Frequency(Max)(kHz): 1000; Rating: Catalog; Regulated Outputs(#): 1; SubFamily: PWM Controller; UVLO Thresholds On/Off(V): 6.75min/6.15min
U3 = LM94022QBIMG: Analog Temperature Sensor with Class-AB Output, 5-pin SC-70; Manufacturer: Texas Instruments; PackageTopMarking: 22Q*XTT; PowerWise: N; CompType: Temp Sensor IC
U6 = TPS560200DBV: 4.5V to 18V Input, 500mA Synchronous Step Down SWIFT Converter, DBV0005A; Alternate Manufacturer: None; Manufacturer: Texas Instruments; SymbolCreator: a0411947; CompType: IC; U/M: EA
U7 = TPS71533DCK: 50 mA, 24 V, 3.2-mA Supply Current Low-Dropout Linear Regulator, DCK0005A; Alternate Manufacturer: None; Manufacturer: Texas Instruments; SymbolCreator: a0799628; CompType: IC; U/M: EA
U8 = TL431AIDBZ: PRECISION PROGRAMMABLE REFERENCE, DBZ0003A; Alternate Manufacturer: None; Manufacturer: Texas Instruments; SymbolCreator: a0412235; CompType: IC; U/M: EA

## Sheet PMP8740 2KW Rev_C Full Bridge Control Section-B Schematic.SchDoc: Full Bridge
size 431 x 279 mm; Date: Not shown in title block; ApprovedBy: Not shown in title block; CheckedBy: Not shown in title block; Author: Not shown in title block; CompanyName: Not shown in title block; DrawnBy: R. Scibilia; Engineer: Not shown in title block; Organization: Not shown in title block; Address1: Not shown in title block; Address2: Not shown in title block; Address3: Not shown in title block; Address4: Not shown in title block; DocumentNumber: 1; Revision: Use project parameter SCH_Rev; SheetNumber: 1; SheetTotal: 1; PageSetup: Record=PageOptions|CenterHorizontal=True|CenterVertical=True|PrintScale=1.00|XCorrection=1.00|YCorrection=1.00|PrintKind=0|BorderSize=5000000|LeftOffset=0|BottomOffset=0|Orientation=2|PaperLength=1000|PaperWidth=1000|Scale=100|PaperSource=15|PrintQuality=600|MediaType=1|DitherType=10|PaperKind=Letter|PrintScaleMode=1
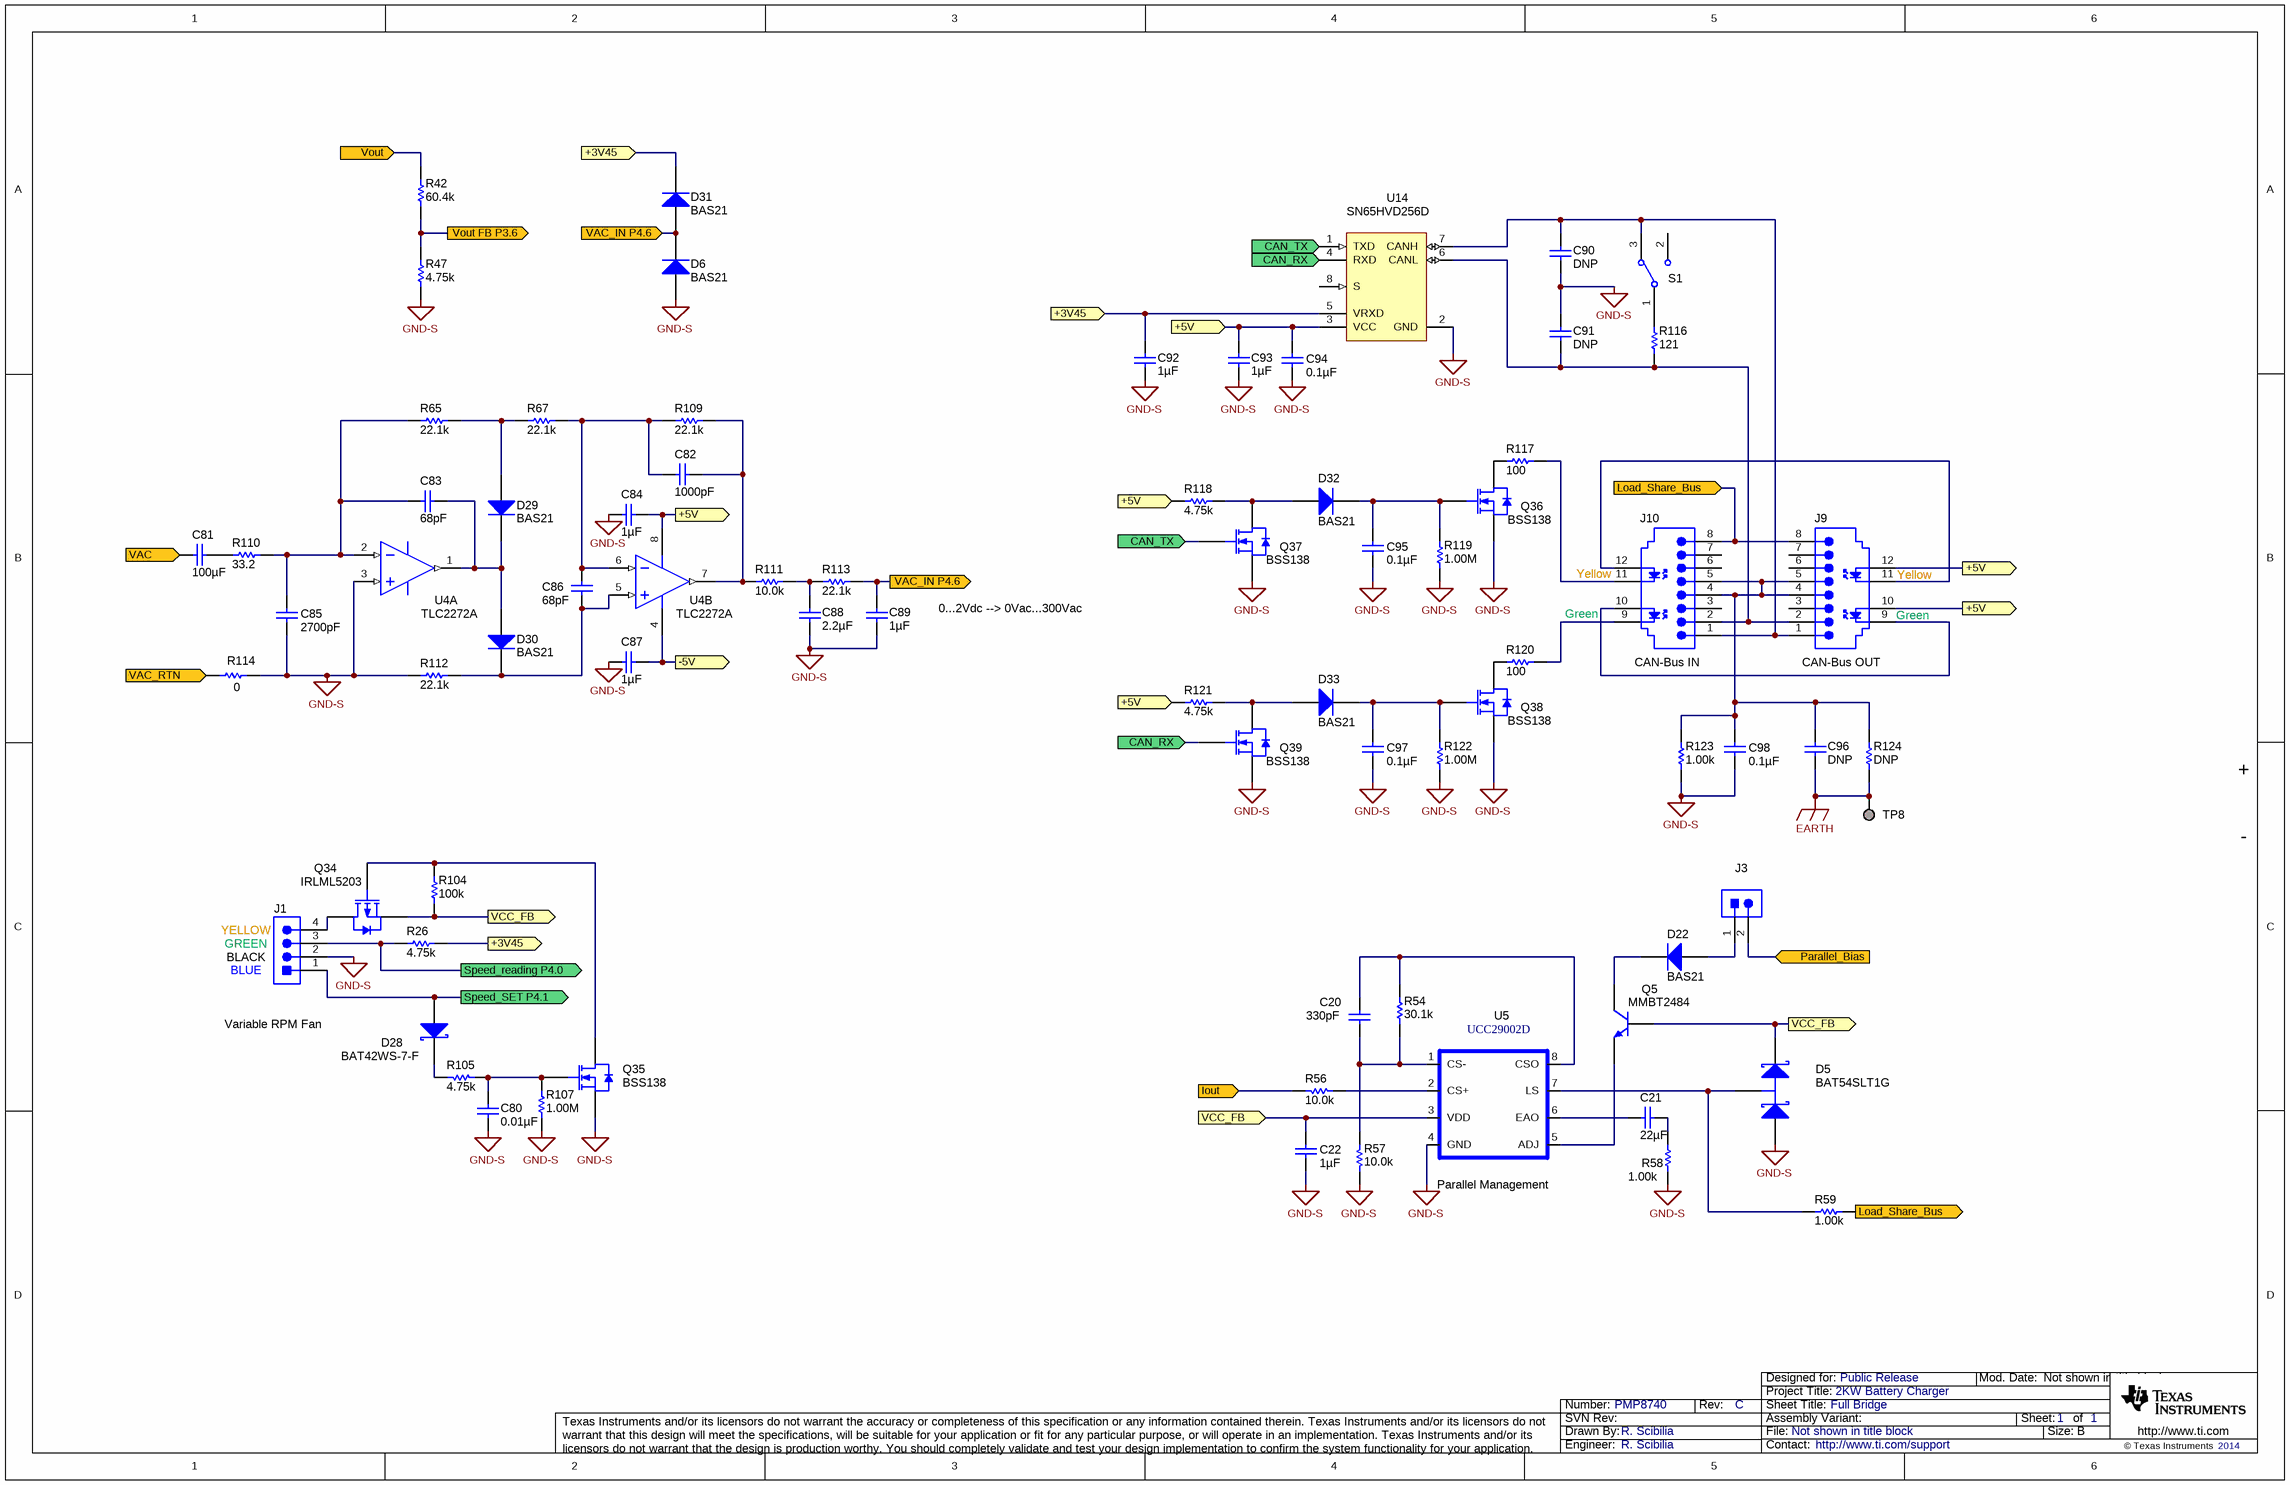
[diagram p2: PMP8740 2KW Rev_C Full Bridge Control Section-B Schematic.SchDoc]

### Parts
C20  ValueDisplayed: 330pF  [0603]  (hidden comment: C1608C0G1H331J)
C21  ValueDisplayed: 22µF  [0805_HV]  (hidden comment: C2012X5R0J226M)
C22  ValueDisplayed: 1µF  [0603]  (hidden comment: C1608X7R1E105K080AB)
C80  ValueDisplayed: 0.01µF  [0603]  (hidden comment: C1608X7R1H103K)
C81  ValueDisplayed: 100µF  [1206_190]  (hidden comment: C3216X5R1A107M160AC)
C82  ValueDisplayed: 1000pF  [0603]  (hidden comment: C1608X7R1H102K)
C83  ValueDisplayed: 68pF  [0603]  (hidden comment: C1608C0G1H680J)
C84  ValueDisplayed: 1µF  [0805_HV]  (hidden comment: C2012X7R1C105K)
C85  ValueDisplayed: 2700pF  [0603]  (hidden comment: C1608C0G1H272J)
C86  ValueDisplayed: 68pF  [0603]  (hidden comment: C1608C0G1H680J)
C87  ValueDisplayed: 1µF  [0805_HV]  (hidden comment: C2012X7R1C105K)
C88  ValueDisplayed: 2.2µF  [0805_HV]  (hidden comment: C2012X7R1C225K)
C89  ValueDisplayed: 1µF  [0805_HV]  (hidden comment: C2012X7R1C105K)
C90  DNP  [0603]
C91  DNP  [0603]
C92  ValueDisplayed: 1µF  [0805_HV]  (hidden comment: C2012X7R1C105K)
C93  ValueDisplayed: 1µF  [0805_HV]  (hidden comment: C2012X7R1C105K)
C94  ValueDisplayed: 0.1µF  [0603]  (hidden comment: C1608X7R1H104K)
C95  ValueDisplayed: 0.1µF  [0603]  (hidden comment: C1608X7R1H104K)
C96  DNP  [0603]
C97  ValueDisplayed: 0.1µF  [0603]  (hidden comment: C1608X7R1H104K)
C98  ValueDisplayed: 0.1µF  [0603]  (hidden comment: C1608X7R1H104K)
D5  BAT54SLT1G  [SOT-23]
D6  value BAS21  [SOT-23]  (hidden comment: BAS21-7-F)
D22  value BAS21  [SOT-23]  (hidden comment: BAS21-7-F)
D28  BAT42WS-7-F  [sod-323]
D29  value BAS21  [SOT-23]  (hidden comment: BAS21-7-F)
D30  value BAS21  [SOT-23]  (hidden comment: BAS21-7-F)
D31  value BAS21  [SOT-23]  (hidden comment: BAS21-7-F)
D32  value BAS21  [SOT-23]  (hidden comment: BAS21-7-F)
D33  value BAS21  [SOT-23]  (hidden comment: BAS21-7-F)
J1  1757268  [Phoenix_1757268]  (value not drawn)
J3  5-146261-1  [CONN_5-146261-1]  (value not drawn)
J9  2-406549-1  [2-406549-1]  (value not drawn)
J10  2-406549-1  [2-406549-1]  (value not drawn)
Q5  MMBT2484  [SOT-23]
Q34  IRLML5203  [SOT-23]
Q35  BSS138  [SOT-23]
Q36  BSS138  [SOT-23]
Q37  BSS138  [SOT-23]
Q38  BSS138  [SOT-23]
Q39  BSS138  [SOT-23]
R26  value 4.75k  [0603]  (hidden comment: CRCW06034K75FKEA)
R42  value 60.4k  [0603]  (hidden comment: CRCW060360K4FKEA)
R47  value 4.75k  [0603]  (hidden comment: CRCW06034K75FKEA)
R54  value 30.1k  [0603]  (hidden comment: CRCW060330K1FKEA)
R56  value 10.0k  [0603]  (hidden comment: CRCW060310K0FKEA)
R57  value 10.0k  [0603]  (hidden comment: CRCW060310K0FKEA)
R58  value 1.00k  [0603]  (hidden comment: CRCW06031K00FKEA)
R59  value 1.00k  [0603]  (hidden comment: CRCW06031K00FKEA)
R65  value 22.1k  [0603]  (hidden comment: CRCW060322K1FKEA)
R67  value 22.1k  [0603]  (hidden comment: CRCW060322K1FKEA)
R104  value 100k  [0603]  (hidden comment: CRCW0603100KFKEA)
R105  value 4.75k  [0603]  (hidden comment: CRCW06034K75FKEA)
R107  ValueDisplayed: 1.00M  [0603]  (hidden comment: CRCW06031M00FKEA)
R109  value 22.1k  [0603]  (hidden comment: CRCW060322K1FKEA)
R110  value 33.2  [0603]  (hidden comment: CRCW060333R2FKEA)
R111  value 10.0k  [0603]  (hidden comment: CRCW060310K0FKEA)
R112  value 22.1k  [0603]  (hidden comment: CRCW060322K1FKEA)
R113  value 22.1k  [0603]  (hidden comment: CRCW060322K1FKEA)
R114  value 0  [0603]  (hidden comment: CRCW06031R00FKEA)
R116  ValueDisplayed: 121  [1206]  (hidden comment: CRCW1206121RFKEA)
R117  ValueDisplayed: 100  [0603]  (hidden comment: CRCW0603100RFKEA)
R118  value 4.75k  [0603]  (hidden comment: CRCW06034K75FKEA)
R119  ValueDisplayed: 1.00M  [0603]  (hidden comment: CRCW06031M00FKEA)
R120  ValueDisplayed: 100  [0603]  (hidden comment: CRCW0603100RFKEA)
R121  value 4.75k  [0603]  (hidden comment: CRCW06034K75FKEA)
R122  ValueDisplayed: 1.00M  [0603]  (hidden comment: CRCW06031M00FKEA)
R123  value 1.00k  [0603]  (hidden comment: CRCW06031K00FKEA)
R124  DNP  [0603]
S1  NK236W  [SW_NK236W]  (value not drawn)
TP8  Suggest using a net name here  [CONN_8600-0-05-80-00-00-03-0]  (value not drawn)
U4  value TLC2272A  [D0008A_N]  (hidden comment: TLC2272ACDA)  (parts A,B of 2)
U5  UCC29002D  [SO8]
U14  SN65HVD256D  [D0008A_L]

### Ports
+3V45, +5V, -5V, CAN_RX, CAN_TX, Iout, Load_Share_Bus, Parallel_Bias, Speed_reading P4.0, Speed_SET P4.1, VAC, VAC_IN P4.6, VAC_RTN, VCC_FB, Vout, Vout FB P3.6

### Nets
EARTH: C96.2 R124.1 TP8.1
GND-S: C22.2 C80.2 C84.2 C85.2 C87.2 C88.2 C89.2 C90.2 C91.1 C92.2 C93.2 C94.2 C95.2 C97.2 C98.2 D5.1(A) D6.1(A) J1.2 Q35.2(S) Q36.2(S) Q37.2(S) Q38.2(S) Q39.2(S) R47.2 R57.1 R58.1 R107.1 R112.1 R114.2 R119.1 R122.1 R123.1 U4.3(IN1+) U5.4(GND) U14.2(GND)
+3V45: C92.1 D31.3(K) R26.2 U14.5(VRXD) ; port +3V45
+5V: C84.1 C93.1 C94.1 J9.10(A1) J9.12(A2) R118.1 R121.1 U4.8(VDD+) U14.3(VCC) ; port +5V
-5V: C87.1 U4.4(VDD-/GND) ; port -5V
CAN_RX: Q39.1(G) U14.4(RXD) ; port CAN_RX
CAN_TX: Q37.1(G) U14.1(TXD) ; port CAN_TX
Iout: R56.2 ; port Iout
Load_Share_Bus: J9.8 J10.8 R59.1 ; port Load_Share_Bus
Parallel_Bias: J3.2 ; port Parallel_Bias
Speed_reading P4.0: J1.3 R26.1 ; port Speed_reading P4.0
Speed_SET P4.1: D28.2(A) J1.1 ; port Speed_SET P4.1
VAC: C81.1 ; port VAC
VAC_IN P4.6: C89.1 D6.3(K) D31.1(A) R113.1 ; port VAC_IN P4.6
VAC_RTN: R114.1 ; port VAC_RTN
VCC_FB: C22.1 D5.2(K) Q5.1(B) Q34.2(S) R104.1 U5.3(VDD) ; port VCC_FB
Vout: R42.2 ; port Vout
Vout FB P3.6: R42.1 R47.1 ; port Vout FB P3.6
NetC20_1: C20.1 R54.2 U5.8(CSO)
NetC20_2: C20.2 R54.1 R57.2 U5.1(CS-)
NetC21_1: C21.1 U5.6(EAO)
NetC21_2: C21.2 R58.2
NetC80_1: C80.1 Q35.1(G) R105.1 R107.2
NetC81_2: C81.2 R110.2
NetC82_1: C82.1 R109.2 R111.1 U4.7(OUT2)
NetC82_2: C82.2 C86.1 R67.2 R109.1 U4.6(IN2-)
NetC83_1: C83.1 C85.1 R65.1 R110.1 U4.2(IN1-)
NetC83_2: C83.2 D29.3(K) D30.1(A) U4.1(OUT1)
NetC86_2: C86.2 D30.3(K) R112.2 U4.5(IN2+)
NetC88_1: C88.1 R111.2 R113.2
NetC90_1: C90.1 J9.1 J10.1 S1.3 U14.7(CANH)
NetC91_2: C91.2 J9.2 J10.2 R116.1 U14.6(CANL)
NetC95_1: C95.1 D32.3(K) Q36.1(G) R119.2
NetC96_1: C96.1 C98.1 J9.4 J9.5 J10.4 J10.5 R123.2 R124.2
NetC97_1: C97.1 D33.3(K) Q38.1(G) R122.2
NetD5_3: D5.3(C) R59.2 U5.7(LS)
NetD22_1: D22.1(A) J3.1
NetD22_3: D22.3(K) Q5.3(C)
NetD28_1: D28.1(K) R105.2
NetD29_1: D29.1(A) R65.2 R67.1
NetD32_1: D32.1(A) Q37.3(D) R118.2
NetD33_1: D33.1(A) Q39.3(D) R121.2
NetJ1_4: J1.4 Q34.3(D)
NetJ9_9: J9.9(K1) J10.10(A1)
NetJ9_11: J9.11(K2) J10.12(A2)
NetJ10_9: J10.9(K1) R120.2
NetJ10_11: J10.11(K2) R117.2
NetQ5_2: Q5.2(E) U5.5(ADJ)
NetQ34_1: Q34.1(G) Q35.3(D) R104.2
NetQ36_3: Q36.3(D) R117.1
NetQ38_3: Q38.3(D) R120.1
NetR56_1: R56.1 U5.2(CS+)
NetR116_2: R116.2 S1.1

Not connected (* = marked no-connect by the designer): J9 3 6 7; J10 3 6 7; S1 2; U14 8(S)

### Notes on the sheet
- (near J10) Yellow
- (near J9) Yellow
- 0...2Vdc --> 0Vac...300Vac
- Green
- (near J9) Green
- (near J10) CAN-Bus IN
- (near J9) CAN-Bus OUT
- +
- -
- (near J1) YELLOW
- (near J1) GREEN
- (near J1) BLACK
- (near J1) BLUE
- (near J1) Variable RPM Fan
- (near U5) Parallel Management

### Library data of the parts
C20 = C1608C0G1H331J: as C9 on sheet PMP8740 2KW Rev_C Full Bridge Control Section-A Schematic
C21 = C2012X5R0J226M: CAP, CERM, 22uF, 6.3V, +/-20%, X5R, 0805; Manufacturer: TDK; Polarized: N; CompType: Capacitor; U/M: EA; Cap_F: 0.000022; Tolerance_%: 20; ESR_Ohm: 0.0018; Value1: 0.0018 ohm; VDC_V: 6.3; TaMin_C: -55; TaMax_C: 85; Cap_Case: 0805
C22 = C1608X7R1E105K080AB: as C3 on sheet PMP8740 2KW Rev_C Full Bridge Control Section-A Schematic
C80 = C1608X7R1H103K: CAP, CERM, 0.01 µF, 50 V, +/- 10%, X7R, 0603; Manufacturer: TDK; Polarized: N; CompType: Capacitor; Value: 0.01uF; U/M: EA; Cap_F: 0.00000001; Tolerance_%: 10; ESR_ohm: 0.0539; Value1: 0.0539 ohm; VDC_V: 50; Value2: 50V; TaMin_C: -55; TaMax_C: 125
C81 = C3216X5R1A107M160AC: CAP, CERM, 100uF, 10V, +/-20%, X5R, 1206_190; Manufacturer: TDK; Polarized: N; CompType: Capacitor; U/M: EA; Cap_F: 0.0001; Tolerance_%: 20; Value1: Unknown; VDC_V: 10; TaMin_C: -55; TaMax_C: 85
C82 = C1608X7R1H102K: CAP, CERM, 1000pF, 50V, +/-10%, X7R, 0603; Manufacturer: TDK; Polarized: N; CompType: Capacitor; U/M: EA; Cap_F: 0.000000001; Tolerance_%: 10; ESR_Ohm: 0.24; Value1: 0.24 ohm; VDC_V: 50; TaMin_C: -55; TaMax_C: 125
C83 C86 = C1608C0G1H680J: CAP, CERM, 68pF, 50V, +/-5%, C0G/NP0, 0603; Manufacturer: TDK; Polarized: N; CompType: Capacitor; U/M: EA; Cap_F: 0.000000000068; Tolerance_%: 5; ESR_Ohm: 0.1724; Value1: 0.1724 ohm; VDC_V: 50; TaMin_C: -55; TaMax_C: 125
C84 C87 C89 C92 C93 = C2012X7R1C105K: CAP, CERM, 1uF, 16V, +/-10%, X7R, 0805; Manufacturer: TDK; Polarized: N; CompType: Capacitor; U/M: EA; Cap_F: 0.000001; Tolerance_%: 10; ESR_Ohm: 0.0075; Value1: 0.0075 ohm; VDC_V: 16; TaMin_C: -55; TaMax_C: 125; Cap_Case: 0805
C85 = C1608C0G1H272J: CAP, CERM, 2700pF, 50V, +/-5%, C0G/NP0, 0603; Manufacturer: TDK; Polarized: N; CompType: Capacitor; U/M: EA; Cap_F: 0.0000000027; Tolerance_%: 5; Value1: Unknown; VDC_V: 50; TaMin_C: -55; TaMax_C: 125
C88 = C2012X7R1C225K: as C4 on sheet PMP8740 2KW Rev_C Full Bridge Control Section-A Schematic
C90 C91 C96 = C1608X7R2A223K: as C5 on sheet PMP8740 2KW Rev_C Full Bridge Control Section-A Schematic
C94 C95 C97 C98 = C1608X7R1H104K: as C2 on sheet PMP8740 2KW Rev_C Full Bridge Control Section-A Schematic
D5 = BAT54SLT1G: Diode, Schottky, 30V, 0.2A, SOT-23; Manufacturer: ON Semiconductor; U/M: EA; Vf_V: 0.8; Value2: 0.8V; Io_A: 0.2; Vr_V: 30; TJmax_C: 150
D6 D22 D29-D33 = BAS21-7-F: as D2 on sheet PMP8740 2KW Rev_C Full Bridge Control Section-A Schematic
D28 = BAT42WS-7-F: as D1 on sheet PMP8740 2KW Rev_C Full Bridge Control Section-A Schematic
J1 = 1757268: Header (shrouded), 5.08 mm, 4x1, R/A, TH; Manufacturer: Phoenix Contact; SymbolCreator: a0412235; U/M: EA
J3 = 5-146261-1: as J11 on sheet PMP8740 2KW Rev_C Full Bridge Control Section-A Schematic
J9 J10 = 2-406549-1: RJ-45, Right Angle, Yellow/Green LED, tab up; Manufacturer: AMP; SymbolCreator: codlsc; CompType: Connector; U/M: EA
Q5 = MMBT2222A, Fairchild Semiconductor: Transistor, NPN, 40V, 0.15A, SOT-23; CompType: BJT; PNP: 0; NPN: 1; Vceo_V: 60; Vcesat1_V: 0.3; IcRated_A: 0.15; HfeMax: 300; TaMin_C: -55; TaMax_C: 150; U/M: EA
Q34 = BSS84-7-F: MOSFET, P-CH, -30 V, -3 A, SOT-23; Manufacturer: Diodes Inc.; Alternate Manufacturer: None; U/M: EA; ChType: P; VdsMax_V: -50; Value1: ? ohm; Value2: ? nC; Vgs_V: 20; IdsMax_A: -0.13
Q35-Q39 = BSS138: as Q1 on sheet PMP8740 2KW Rev_C Full Bridge Control Section-A Schematic
R26 R47 R105 R118 R121 = CRCW06034K75FKEA: as R25 on sheet PMP8740 2KW Rev_C Full Bridge Control Section-A Schematic
R42 = CRCW060360K4FKEA: as R15 on sheet PMP8740 2KW Rev_C Full Bridge Control Section-A Schematic
R54 = CRCW060330K1FKEA: RES, 30.1k ohm, 1%, 0.1W, 0603; Manufacturer: Vishay-Dale; CompType: Resistor; Res_ohm: 30100; Value_Code: 30k1; Tolerance_%: 1; Power_W: 0.1; VDC_V: 75; TempCo: 100 ppm/C; EIA_Code: E96; U/M: EA
R56 R57 R111 = CRCW060310K0FKEA: as R2 on sheet PMP8740 2KW Rev_C Full Bridge Control Section-A Schematic
R58 R59 R123 = CRCW06031K00FKEA: as R27 on sheet PMP8740 2KW Rev_C Full Bridge Control Section-A Schematic
R65 R67 R109 R112 R113 = CRCW060322K1FKEA: RES, 22.1k ohm, 1%, 0.1W, 0603; Manufacturer: Vishay-Dale; CompType: Resistor; Res_ohm: 22100; Value_Code: 22k1; Tolerance_%: 1; Power_W: 0.1; VDC_V: 75; TempCo: 100 ppm/C; EIA_Code: E96; U/M: EA
R104 = CRCW0603100KFKEA: as R4 on sheet PMP8740 2KW Rev_C Full Bridge Control Section-A Schematic
R107 R119 R122 = CRCW06031M00FKEA: RES, 1.00 M, 1%, 0.1 W, 0603; Manufacturer: Vishay-Dale; CompType: Resistor; Value: 1.00Meg; Res_ohm: 1000000; Value_Code: 1M00; Tolerance_%: 1; Power_W: 0.1; Value2: 0.1W; VDC_V: 75; TempCo: 100 ppm/C; EIA_Code: E96; U/M: EA
R110 = CRCW060333R2FKEA: as R38 on sheet PMP8740 2KW Rev_C Full Bridge Control Section-A Schematic
R114 = CRCW06031R00FKEA: as R1 on sheet PMP8740 2KW Rev_C Full Bridge Control Section-A Schematic
R116 = CRCW1206121RFKEA: RES, 121, 1%, 0.25 W, 1206; Manufacturer: Vishay-Dale; CompType: Resistor; Value: 121; Value_Code: 121R; Tolerance_%: 1; Power_W: 0.25; Value2: 0.25W; VDC_V: 200; TempCo: 100 ppm/C; EIA_Code: E96; U/M: EA
R117 R120 = CRCW0603100RFKEA: RES, 100, 1%, 0.1 W, 0603; Manufacturer: Vishay-Dale; CompType: Resistor; Value: 100; Value_Code: 100R; Tolerance_%: 1; Power_W: 0.1; Value2: 0.1W; VDC_V: 75; TempCo: 100 ppm/C; EIA_Code: E96; U/M: EA
R124 = CRCW06031K00FKEA: CompType: Resistor; Res_ohm: 1000; Value_Code: 1k00; Tolerance_%: 1; Value1: 1%; Power_W: 0.1; Value2: 0.1W; VDC_V: 75; TempCo: 100 ppm/C; EIA_Code: E96; U/M: EA
S1 = NK236W: Switch, Slide Flush actuator, SPDT, R/A, TH; Manufacturer: APEM; SymbolCreator: a0412235; VDC_V: 12; SwitchFunction: On-On; PositionCount: 1; CurrentRating_mA: 500
TP8 = 8600-0-05-80-00-00-03-0: PCB Pin, solderless Pressfit, Tin over Nickel; Manufacturer: Mill-Max; CompType: PCB Pin; U/M: EA
U4 = TLC2272ACD: Advanced LinCMOS(TM) Rail-to-Rail Dual Operational Amplifier, 4.4 to 16 V, 0 to 70 degC, 8-pin SOIC (D0008A), Green (RoHS & no Sb/Br); Manufacturer: Texas Instruments; Alternate Manufacturer: None; Alternate PartNumber: Equivalent; CMRR(Min)(dB): 70; GBW(Typ)(MHz): 2.18; IIB(Max)(pA): 60; Iq per channel(Max)(mA): 1.5; Number of Channels: 2; Packing: TUBE; Rating: Catalog; Slew Rate(Typ)(V/us): 3.6; Sub Family: Low Noise Amp (<=10nV/rtHz), Precision Amplifier; Total Supply Voltage(Max)(+5V is 5, +/-5V is 10): 16; Total Supply Voltage(Min)(+5V is 5, +/-5V is 10): 4.4; Vio (25C)(Max)(mV): 0.95
U5 = UCC2900XD: IC, Advance 8-p Load -Share Controller.; Manufacturer: TI; Alternate Manufacturer: None; Area: 75900
U14 = SN65HVD256D: CAN Transceiver with Fast Loop Times for Highly Loaded Networks, 85 mA, 5 V, -40 to 125 degC, 8-pin SOIC (D), Green (RoHS & no Sb/Br); Manufacturer: Texas Instruments; Alternate Manufacturer: None; Alternate PartNumber: Equivalent; Drivers Per Package: 1; Bus Fault Voltage(V): -27 to 40; ICC(Max)(mA): 85; Supply Voltage(s)(V): 5; Rating: Catalog

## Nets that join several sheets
EARTH: PMP8740 2KW Rev_C Full Bridge Power Stage Schematic (J8.2 TP7.1), PMP8740 2KW Rev_C Full Bridge Control Section-B Schematic (C96.2 R124.1 TP8.1)
GND-S: PMP8740 2KW Rev_C Full Bridge Power Stage Schematic (51 pins), PMP8740 2KW Rev_C Full Bridge Control Section-A Schematic (58 pins), PMP8740 2KW Rev_C Full Bridge Control Section-B Schematic (35 pins)
+3V45: PMP8740 2KW Rev_C Full Bridge Power Stage Schematic (R48.2 R55.1), PMP8740 2KW Rev_C Full Bridge Control Section-A Schematic (10 pins), PMP8740 2KW Rev_C Full Bridge Control Section-B Schematic (C92.1 D31.3 R26.2 U14.5)
+5V: PMP8740 2KW Rev_C Full Bridge Control Section-A Schematic (8 pins), PMP8740 2KW Rev_C Full Bridge Control Section-B Schematic (9 pins)
-5V: PMP8740 2KW Rev_C Full Bridge Control Section-A Schematic (C73.1 D24.2 D26.2), PMP8740 2KW Rev_C Full Bridge Control Section-B Schematic (C87.1 U4.4)
CAN_RX: PMP8740 2KW Rev_C Full Bridge Control Section-A Schematic (J2.2), PMP8740 2KW Rev_C Full Bridge Control Section-B Schematic (Q39.1 U14.4)
CAN_TX: PMP8740 2KW Rev_C Full Bridge Control Section-A Schematic (J2.3), PMP8740 2KW Rev_C Full Bridge Control Section-B Schematic (Q37.1 U14.1)
CT+: PMP8740 2KW Rev_C Full Bridge Power Stage Schematic (R69.2 T1.1), PMP8740 2KW Rev_C Full Bridge Control Section-A Schematic (D2.1)
CT-: PMP8740 2KW Rev_C Full Bridge Power Stage Schematic (R69.1 T1.4), PMP8740 2KW Rev_C Full Bridge Control Section-A Schematic (R34.1 R36.1)
Iout: PMP8740 2KW Rev_C Full Bridge Power Stage Schematic (C66.1 R100.1 U11.1), PMP8740 2KW Rev_C Full Bridge Control Section-A Schematic (R4.1 R35.2 R39.1 TP6.1), PMP8740 2KW Rev_C Full Bridge Control Section-B Schematic (R56.2)
OUT-A: PMP8740 2KW Rev_C Full Bridge Power Stage Schematic (U13.4), PMP8740 2KW Rev_C Full Bridge Control Section-A Schematic (U2.22)
OUT-B: PMP8740 2KW Rev_C Full Bridge Power Stage Schematic (U13.2), PMP8740 2KW Rev_C Full Bridge Control Section-A Schematic (U2.21)
OUT-C: PMP8740 2KW Rev_C Full Bridge Power Stage Schematic (U12.4), PMP8740 2KW Rev_C Full Bridge Control Section-A Schematic (U2.20)
OUT-D: PMP8740 2KW Rev_C Full Bridge Power Stage Schematic (U12.2), PMP8740 2KW Rev_C Full Bridge Control Section-A Schematic (U2.19)
OUT-E: PMP8740 2KW Rev_C Full Bridge Power Stage Schematic (U9.2 U9.4), PMP8740 2KW Rev_C Full Bridge Control Section-A Schematic (U2.18)
OUT-F: PMP8740 2KW Rev_C Full Bridge Power Stage Schematic (U10.2 U10.4), PMP8740 2KW Rev_C Full Bridge Control Section-A Schematic (U2.17)
Parallel_Bias: PMP8740 2KW Rev_C Full Bridge Control Section-A Schematic (C5.1 R13.2 R14.2), PMP8740 2KW Rev_C Full Bridge Control Section-B Schematic (J3.2)
Pre-Charge P2.2: PMP8740 2KW Rev_C Full Bridge Power Stage Schematic (R84.1), PMP8740 2KW Rev_C Full Bridge Control Section-A Schematic (J2.18)
Reverse Polarity P3.3: PMP8740 2KW Rev_C Full Bridge Power Stage Schematic (D4.1 R55.2), PMP8740 2KW Rev_C Full Bridge Control Section-A Schematic (J2.14)
Speed_reading P4.0: PMP8740 2KW Rev_C Full Bridge Control Section-A Schematic (J2.11), PMP8740 2KW Rev_C Full Bridge Control Section-B Schematic (J1.3 R26.1)
Speed_SET P4.1: PMP8740 2KW Rev_C Full Bridge Control Section-A Schematic (J2.10), PMP8740 2KW Rev_C Full Bridge Control Section-B Schematic (D28.2 J1.1)
V-FLOAT: PMP8740 2KW Rev_C Full Bridge Power Stage Schematic (5 pins), PMP8740 2KW Rev_C Full Bridge Control Section-A Schematic (D23.1)
VAC: PMP8740 2KW Rev_C Full Bridge Control Section-A Schematic (J5.5), PMP8740 2KW Rev_C Full Bridge Control Section-B Schematic (C81.1)
VAC_IN P4.6: PMP8740 2KW Rev_C Full Bridge Control Section-A Schematic (J2.39), PMP8740 2KW Rev_C Full Bridge Control Section-B Schematic (C89.1 D6.3 D31.1 R113.1)
VAC_RTN: PMP8740 2KW Rev_C Full Bridge Control Section-A Schematic (J5.10), PMP8740 2KW Rev_C Full Bridge Control Section-B Schematic (R114.1)
VCC_FB: PMP8740 2KW Rev_C Full Bridge Power Stage Schematic (16 pins), PMP8740 2KW Rev_C Full Bridge Control Section-A Schematic (10 pins), PMP8740 2KW Rev_C Full Bridge Control Section-B Schematic (6 pins)
Vout: PMP8740 2KW Rev_C Full Bridge Power Stage Schematic (30 pins), PMP8740 2KW Rev_C Full Bridge Control Section-A Schematic (R12.1 TP3.1), PMP8740 2KW Rev_C Full Bridge Control Section-B Schematic (R42.2)
Vout FB P3.6: PMP8740 2KW Rev_C Full Bridge Control Section-A Schematic (J2.1), PMP8740 2KW Rev_C Full Bridge Control Section-B Schematic (R42.1 R47.1)

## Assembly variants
001: not fitted FID1 FID2 FID3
